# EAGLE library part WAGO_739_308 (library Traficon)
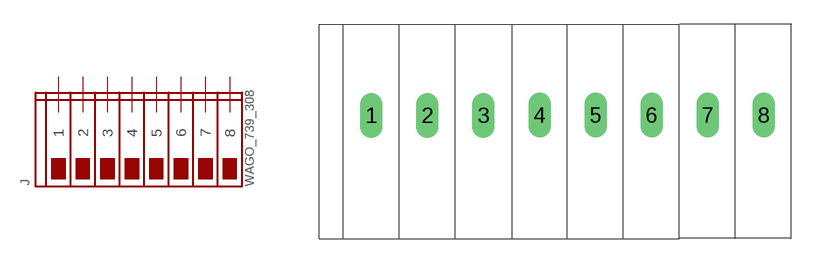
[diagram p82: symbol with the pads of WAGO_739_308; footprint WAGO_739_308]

Designator prefix J

## WAGO_739_308  [WAGO_739_308]
1  1
2  2
3  3
4  4
5  5
6  6
7  7
8  8

## Footprint WAGO_739_308 (pad centres in mm)
drill 0.9 long: 1 -0.009,7.686; 2 3.491,7.686; 3 6.991,7.686; 4 10.5,7.7; 5 14,7.7; 6 17.5,7.7; 7 21,7.7; 8 24.5,7.7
